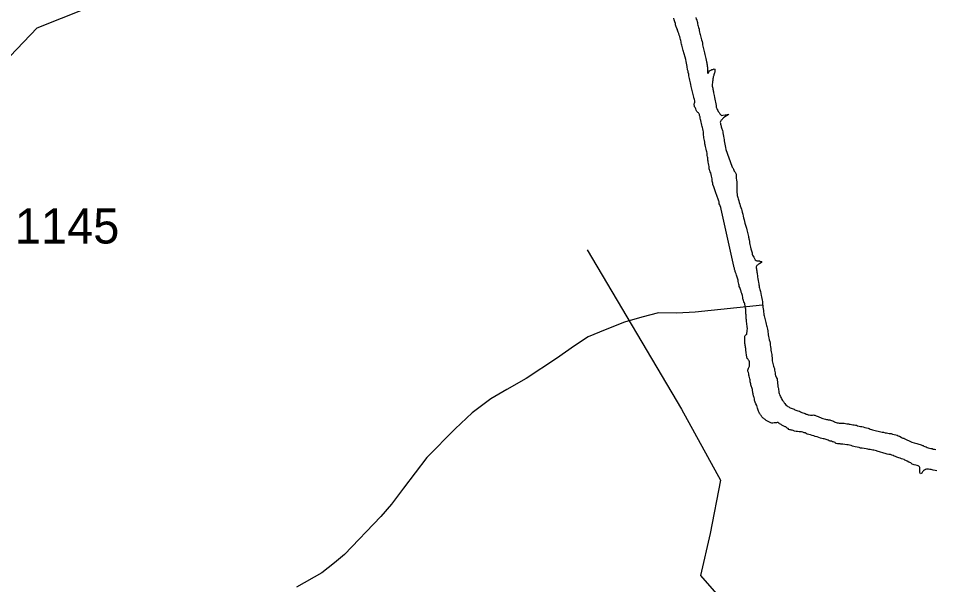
# Model space of a CAD drawing. Extents: x 1662474 to 1856135, y 779280 to 917889.
# Drawn here: x 1727638 to 1730904, y 804884 to 806900 of the extents above; entities that cross this region are included whole.
import ezdxf

# ---------------------------------------------------------------- set-up
doc = ezdxf.new("R2010")
doc.units = 0
for name, color, linetype in [('Exist Hydrographic Lake Shore', 7, 'Continuous'), ('Exist Hydrographic Misc Water Feature', 7, 'Continuous'), ('Exist Road Secondary Type 51 Number Label', 7, 'Continuous'), ('Exist Utilities Electrical Transmission Line', 7, 'Continuous')]:
    doc.layers.add(name, color=color, linetype=linetype)

msp = doc.modelspace()

# ---------------------------------------------------------------- linework, layer by layer
at = {"layer": 'Exist Hydrographic Lake Shore'}
for points in [[(1730046.1, 806584.9), (1730045.4, 806588.1), (1730044.2, 806590.9), (1730044.2, 806593.3), (1730044.9, 806594.9), (1730046.1, 806597.8), (1730046.6, 806600.9), (1730046.4, 806605.6), (1730045.4, 806610.3), (1730044.2, 806614), (1730043.5, 806616.4), (1730042.8, 806619.2), (1730041.9, 806623.8), (1730040.9, 806628.4), (1730040.1, 806633.2), (1730038.8, 806637.9), (1730037.8, 806642.4), (1730035.9, 806647.1), (1730034.9, 806652.3), (1730033.5, 806657.6), (1730032.8, 806663.6), (1730031.8, 806669.7), (1730030.1, 806674.9), (1730029.4, 806679.9), (1730028.2, 806685.1), (1730027.2, 806690.1), (1730025.9, 806695.4), (1730024.9, 806700.6), (1730023.2, 806706.7), (1730022.5, 806711.6), (1730020.9, 806716.4), (1730020.4, 806720.3), (1730019.6, 806724.5), (1730019.4, 806728.7), (1730018.2, 806733.9), (1730017.2, 806740), (1730015.6, 806746.3), (1730014.4, 806752.9), (1730012, 806761.2), (1730008.9, 806773.6), (1730005.1, 806785.7), (1730003.4, 806794.6), (1730002, 806799.8), (1730000.8, 806804.3), (1729999.9, 806808), (1729998.6, 806811.9), (1729997.6, 806816.1), (1729996.8, 806820.3), (1729995.8, 806824.8), (1729994.6, 806829.5), (1729992.9, 806834.8), (1729991.5, 806839.8), (1729989.8, 806845.2), (1729987.6, 806850), (1729986.2, 806853.9), (1729985.2, 806857.6), (1729984.5, 806860.4), (1729983.1, 806863.4), (1729982.1, 806866.8), (1729980.8, 806869.6), (1729979.5, 806873.1), (1729978.4, 806876.8), (1729977.4, 806881.8), (1729975.2, 806887.5), (1729973.1, 806894.1), (1729971.6, 806900.1)], [(1730050.4, 806903), (1730051.9, 806896.9), (1730053.8, 806892.8), (1730054.8, 806888), (1730056.1, 806884.4), (1730056.6, 806879.9), (1730058, 806875.4), (1730059.2, 806871.2), (1730060.2, 806866.5), (1730061.9, 806861.2), (1730062.6, 806856.2), (1730064, 806850.8), (1730064.8, 806846.1), (1730066.1, 806841.8), (1730066.9, 806837.6), (1730067.9, 806833.2), (1730069.8, 806828.4), (1730070.8, 806822.9), (1730072.4, 806816.9), (1730073.6, 806811.4), (1730074.5, 806805.9), (1730075.5, 806801.1), (1730076.9, 806796.4), (1730077.9, 806791.2), (1730079.2, 806786.4), (1730080, 806782), (1730081.2, 806777.2), (1730082.4, 806771.2), (1730083.6, 806765.8), (1730084.8, 806761.8), (1730086.2, 806757.1), (1730087.6, 806751), (1730088.4, 806745.2), (1730089.1, 806740.8), (1730090, 806737.6), (1730090.5, 806733.9), (1730091.2, 806729.5), (1730091.5, 806725.3), (1730092, 806721.1), (1730092, 806718.2), (1730092.4, 806715.1), (1730092, 806711.1), (1730092, 806705.6), (1730093.6, 806702.8), (1730095.8, 806705.9), (1730097.2, 806709), (1730099.1, 806712.4), (1730101.2, 806714.2), (1730104.1, 806715.6), (1730107.5, 806717.2), (1730110.8, 806717.7), (1730112.8, 806719.2), (1730116.2, 806719.5), (1730118, 806719.2)], [(1730118, 806719.2), (1730118.2, 806715.6), (1730118.2, 806713.2), (1730118.2, 806710.9), (1730117.5, 806708.5), (1730116.8, 806705.6), (1730116, 806702.4), (1730114.6, 806699.1), (1730114.1, 806696.2), (1730112.8, 806694.3), (1730112, 806691.4), (1730111.5, 806688), (1730110.8, 806684.4), (1730110.4, 806681.8), (1730110.4, 806678.6), (1730110.1, 806674.9), (1730109.4, 806670.2), (1730108.9, 806665.8), (1730108.9, 806661.2), (1730108.6, 806658.4), (1730109.4, 806655.2), (1730110.4, 806651.6), (1730111.2, 806647.9), (1730112.2, 806644.4), (1730112.5, 806641.3), (1730112.8, 806637.9), (1730113.4, 806634.5), (1730114.4, 806630), (1730115.6, 806624.8), (1730116.8, 806618.2), (1730118, 806611.6), (1730119.4, 806605.9), (1730120.4, 806600.9), (1730121.8, 806595.1), (1730122.5, 806589.1), (1730123.2, 806583.6), (1730125.1, 806578.9), (1730126.1, 806575.2), (1730128.2, 806571.8), (1730130.4, 806568.1), (1730133.2, 806564.4), (1730135.9, 806559.4), (1730138.8, 806556), (1730141.6, 806554.4), (1730146.6, 806554.7), (1730154.8, 806556), (1730162.6, 806557.1), (1730166.4, 806558.1), (1730165.2, 806555.8), (1730162.4, 806553.9), (1730157.1, 806551.3), (1730151.9, 806547.9), (1730148.8, 806546.1), (1730147.4, 806544.4), (1730145.6, 806542.4), (1730144.2, 806540.2), (1730142.8, 806538.7), (1730141.1, 806537.4), (1730139.2, 806534.8), (1730137.8, 806532.1), (1730137.2, 806529.2), (1730137.8, 806526.4), (1730138.2, 806522.7), (1730139.2, 806519.5), (1730140.1, 806516.6), (1730140.9, 806513.2), (1730141.9, 806510.1), (1730143.2, 806506.9), (1730144, 806503.5), (1730145.4, 806499.9), (1730145.9, 806495.6), (1730146.6, 806491.7), (1730148, 806486.8), (1730148.8, 806480.2), (1730149.8, 806473.6), (1730150.9, 806468.9), (1730151.6, 806464.1), (1730152.4, 806458.1), (1730154, 806452.1), (1730154.8, 806446.1), (1730156.1, 806440), (1730157.1, 806432.4), (1730178.4, 806373.6), (1730179.8, 806370.4), (1730182.4, 806367.1), (1730184.8, 806362.8), (1730186.2, 806359.2), (1730187.4, 806355.5), (1730190, 806351.8), (1730192.4, 806347.9), (1730193.9, 806344.8), (1730194.1, 806341.1), (1730194.4, 806336.3), (1730194.4, 806330.8), (1730195.2, 806323.8), (1730195.8, 806317.7), (1730196, 806312.4), (1730196, 806307.8), (1730196, 806302.5), (1730196.2, 806296.4)], [(1730208.1, 805938.7), (1730206.5, 805942.1), (1730204.6, 805945.8), (1730204.1, 805950), (1730202.9, 805953.7), (1730202, 805958.4), (1730201.2, 805963.1), (1730200.5, 805967.3), (1730200.2, 805971.5), (1730199.1, 805975.2), (1730197.6, 805978.6), (1730196, 805982.2), (1730194.6, 805985.9), (1730193.6, 805990.1), (1730192, 805995.1), (1730190.8, 805999.1), (1730190, 806000.9), (1730188.6, 806006.4), (1730187.6, 806011.1), (1730186.2, 806014.8), (1730185.5, 806018.2), (1730141.1, 806220.3), (1730139.2, 806226.9), (1730137.5, 806231.9), (1730135.6, 806236.3), (1730134, 806240), (1730133.5, 806243.2), (1730133.2, 806246.1), (1730132, 806249.2), (1730130.9, 806252.1), (1730130.1, 806256), (1730126.8, 806265.8), (1730120.6, 806282.8), (1730114.4, 806300.1), (1730111.2, 806308.5), (1730110.8, 806312.7), (1730109.6, 806316.1), (1730108.9, 806319.6), (1730108.9, 806324), (1730108.4, 806327.9), (1730107.5, 806332.9), (1730106.5, 806338.4), (1730104.6, 806344.2), (1730103.4, 806349.7), (1730101.2, 806353.9), (1730099.9, 806357.6), (1730098.6, 806360.5), (1730098.1, 806363.6), (1730098.1, 806367.6), (1730097.6, 806372.6), (1730096.2, 806377.6), (1730095.8, 806383.3), (1730094.6, 806387.2), (1730093.9, 806390.9), (1730093.6, 806395.1), (1730093.4, 806398.8), (1730092.6, 806402.8), (1730092.4, 806406.9), (1730091.2, 806411.9), (1730090.8, 806416.6), (1730090.5, 806420.1), (1730089.8, 806424.2), (1730088.1, 806428.4), (1730087.6, 806433.9), (1730086.2, 806439.2), (1730085.2, 806443.9), (1730083.9, 806448.9), (1730082.9, 806453.6), (1730082.1, 806458.9), (1730080.8, 806464.4), (1730080, 806469.1), (1730079.2, 806474.1), (1730078.4, 806479.4), (1730077.6, 806484.1), (1730077.4, 806488.1), (1730077.4, 806491.7), (1730077.4, 806495.6), (1730076.2, 806500.4), (1730075.2, 806505.9), (1730074, 806510.9), (1730072.9, 806515.1), (1730072.1, 806519.2), (1730070.2, 806524.8), (1730068.8, 806530), (1730067.9, 806535.6), (1730066.9, 806539.8), (1730065.8, 806544.4), (1730065.2, 806548.9), (1730064, 806553.4), (1730062.9, 806557.1), (1730061.9, 806559.2), (1730061.4, 806561.2), (1730059.5, 806562.8), (1730058, 806564.1), (1730056.4, 806565.8), (1730054.2, 806568.4), (1730052.1, 806572.8), (1730050.1, 806578.1), (1730047.8, 806581.8), (1730046.1, 806584.9)], [(1730196.2, 806296.4), (1730196.8, 806291.7), (1730196.8, 806286.2), (1730196.8, 806279.9), (1730197, 806273.6), (1730197.2, 806269.1), (1730198.4, 806266), (1730199.6, 806262.3), (1730201.2, 806257.6), (1730203.4, 806250.5), (1730204.6, 806243.9), (1730206.8, 806237.9), (1730208.4, 806232.4), (1730210.4, 806226.1), (1730212.5, 806220.1), (1730214.1, 806215.6), (1730215.6, 806210.4), (1730217.2, 806203.2), (1730218.9, 806195.4), (1730219.9, 806190.1), (1730221.2, 806185.9), (1730222.2, 806182), (1730223.2, 806177.2), (1730224.9, 806170.7), (1730226.8, 806163.6), (1730228, 806159.7), (1730229.4, 806156.8), (1730230.4, 806153.1), (1730232.5, 806146.8), (1730234.2, 806137.1), (1730236.4, 806127.9), (1730238, 806123.2), (1730237.8, 806121.1), (1730238.8, 806116.9), (1730239.5, 806114.8), (1730240.4, 806111.1), (1730240.9, 806105.6), (1730241.1, 806100.4), (1730242.5, 806094.9), (1730243.5, 806090.1), (1730245.4, 806085.7), (1730246.6, 806079.9), (1730248.8, 806072.3), (1730250.4, 806065.2), (1730251.4, 806060.2), (1730252.6, 806056.8), (1730254.2, 806053.7), (1730256.4, 806050), (1730259.5, 806044.8), (1730262.1, 806040), (1730265, 806037.9), (1730267.4, 806036.6), (1730270.8, 806037.1), (1730274.5, 806036.3), (1730277.4, 806036.3), (1730280.5, 806034.5), (1730282.4, 806034), (1730285.8, 806034.2), (1730283.1, 806030.3), (1730280.8, 806028.4), (1730278.4, 806026.6), (1730275.2, 806025.1), (1730272.4, 806023.2), (1730270, 806021.6), (1730267.9, 806019.6), (1730266.9, 806017.7), (1730265.5, 806014.8), (1730265.5, 806011.7), (1730266.1, 806008.2), (1730266.9, 806005.1), (1730267.1, 806000.9), (1730267.6, 805996.2), (1730268.4, 805992.2), (1730269.2, 805989.1), (1730269.8, 805984.9), (1730270.2, 805979.4), (1730271.6, 805972.8), (1730272.6, 805966.2), (1730274, 805959.7), (1730274.5, 805955), (1730274.8, 805951.6), (1730275.5, 805947.1), (1730276, 805943.2), (1730277.4, 805939.8), (1730278.4, 805934.8), (1730280, 805927.7), (1730281.5, 805920.3), (1730282.9, 805913.5), (1730283.9, 805908), (1730285.2, 805902.5), (1730286.2, 805896.7), (1730287.4, 805892), (1730287.6, 805887.2), (1730288.1, 805882.8), (1730288.6, 805878.1), (1730289.1, 805872.3), (1730290, 805866), (1730290.8, 805859.9), (1730291.8, 805854.4), (1730292, 805849.4)], [(1730256.6, 805552.9), (1730256.1, 805556.1), (1730254.5, 805561.8), (1730254, 805563.9), (1730253.8, 805567.3), (1730253.2, 805570.2), (1730252.6, 805572.6), (1730252.4, 805575.7), (1730251.6, 805578.9), (1730250.4, 805582.2), (1730249.2, 805585.7), (1730248.2, 805588.8), (1730247.8, 805592.2), (1730246.6, 805595.7), (1730245.6, 805599.1), (1730244.8, 805602.5), (1730244, 805606.2), (1730244, 805610.4), (1730244, 805613.2), (1730243.2, 805616.9), (1730241.6, 805621.6), (1730240.1, 805626.4), (1730239.5, 805630.3), (1730238.8, 805634.8), (1730238, 805639.5), (1730235.9, 805644.5), (1730235.6, 805647.4), (1730236.4, 805650.8), (1730238, 805654.4), (1730240.1, 805659.2), (1730241.1, 805662.3), (1730241.9, 805666), (1730241.9, 805669.7), (1730241.6, 805673.6), (1730240.9, 805677.6), (1730240.1, 805680.4), (1730238.2, 805683.6), (1730236.6, 805685.7), (1730234.9, 805687.5), (1730233.2, 805689.6), (1730232, 805694.9), (1730230.6, 805700.4), (1730230.4, 805703.6), (1730229.6, 805707.5), (1730229.4, 805712.2), (1730228.2, 805717.7), (1730228, 805721.9), (1730227.8, 805724.8), (1730227.2, 805728.5), (1730226.8, 805731.9), (1730226.5, 805735.6), (1730225.6, 805739.2), (1730225.1, 805742.1), (1730224.4, 805746.3), (1730224.4, 805751.3), (1730224.4, 805755.8), (1730224.9, 805759.4), (1730224.9, 805762.3), (1730224.4, 805766), (1730224.4, 805768.4), (1730226.5, 805770.4), (1730228.8, 805772.8), (1730230.6, 805774.7), (1730232, 805776), (1730232.2, 805779.6), (1730232.5, 805782.2), (1730232.8, 805784.1), (1730233.5, 805787), (1730233.5, 805789.4), (1730233.8, 805794.9), (1730233.2, 805803), (1730232, 805812.8), (1730230.6, 805821.9), (1730230.4, 805826.9), (1730230.1, 805830.3), (1730229.6, 805836.1), (1730229.6, 805841.6), (1730229.4, 805844.8), (1730228.8, 805848.4), (1730228.2, 805855.5), (1730228, 805861.6), (1730227.8, 805865.2), (1730227.2, 805868.6), (1730226.5, 805873.4), (1730225.6, 805878.1), (1730224.9, 805880.4), (1730224.4, 805883.1), (1730223.2, 805887), (1730221.8, 805891.2), (1730219.9, 805895.4), (1730219.4, 805898.8), (1730218.2, 805901.9), (1730217.2, 805906.4), (1730216, 805913.5), (1730213.6, 805920.1), (1730212.2, 805925.3), (1730211.8, 805928.8), (1730210.8, 805931.6), (1730209.4, 805934.5), (1730208.1, 805938.7)], [(1730292, 805849.4), (1730292.9, 805844.5), (1730293.6, 805841.1), (1730294.4, 805836.3), (1730295.8, 805831.1), (1730297.2, 805826.4), (1730298.4, 805821.9), (1730299.6, 805817.7), (1730300.8, 805811.7), (1730302, 805806.7), (1730302.9, 805802.8), (1730304.4, 805798.3), (1730305.5, 805793.6), (1730306.5, 805788.1), (1730306.8, 805783.1), (1730307.5, 805777.6), (1730308.4, 805772.8), (1730309.6, 805767.6), (1730310.8, 805762.1), (1730312, 805756), (1730313.6, 805749.8), (1730314.6, 805743.7), (1730315.6, 805737.6), (1730316.5, 805731.1), (1730317.2, 805724.6), (1730317.8, 805718.8), (1730318.9, 805713.2), (1730319.6, 805707.8), (1730320.4, 805702.8), (1730320.6, 805697.2), (1730321.8, 805691.8), (1730322, 805685.9), (1730322.5, 805680.9), (1730323.5, 805676.2), (1730324.1, 805671.5), (1730325.1, 805666.2), (1730326.4, 805662.3), (1730328, 805658.4), (1730329.9, 805653.1), (1730330.6, 805648.1), (1730332, 805642.9), (1730332.5, 805637.9), (1730332.8, 805632.4), (1730334, 805627.9), (1730335.9, 805624), (1730338, 805620.3), (1730339.5, 805616.4), (1730340.4, 805611.7), (1730341.1, 805605.6), (1730341.6, 805600.1), (1730341.9, 805594.4), (1730342.5, 805588.8), (1730343.2, 805585.4), (1730344.2, 805581.2), (1730344.8, 805577.3), (1730345.4, 805572.8), (1730346.4, 805568.6), (1730347.4, 805564.4), (1730348.2, 805562.1), (1730349.5, 805557.6), (1730351.4, 805553.9), (1730353, 805550.5), (1730354.8, 805547.1), (1730356.6, 805543.4), (1730359.2, 805539.2), (1730361.9, 805535.6), (1730364.5, 805531.9), (1730366.9, 805528.8), (1730369.8, 805525.9), (1730372.4, 805522.4), (1730375.2, 805520.3), (1730378.4, 805518), (1730381.2, 805516.9), (1730383.9, 805515.1), (1730386.8, 805514.1), (1730389.8, 805512.8), (1730393.4, 805511.4), (1730396.8, 805510.1), (1730399.9, 805508.2), (1730402.5, 805506.9), (1730405.8, 805505.6), (1730409.6, 805504.3), (1730414.1, 805502.8), (1730418.9, 805501.2), (1730423.2, 805499.1), (1730427.2, 805497.2), (1730431.6, 805495.4), (1730435.6, 805494.1), (1730439.2, 805492.8), (1730442.8, 805491.4), (1730446.1, 805490.4), (1730450, 805488.8), (1730454, 805488.3), (1730458.5, 805487.5), (1730462.4, 805487.2), (1730465.5, 805487.2), (1730468.8, 805488.1), (1730471.6, 805487.8), (1730474, 805487.2), (1730476.2, 805485.7)], [(1730563.8, 805384.9), (1730559.5, 805385.2), (1730554.8, 805385.4), (1730550.4, 805386.2), (1730547.8, 805388.1), (1730545.9, 805389.9), (1730542.5, 805391.2), (1730539.5, 805392.5), (1730537.2, 805393.1), (1730534.9, 805394.4), (1730532, 805394.4), (1730528.2, 805395.1), (1730524.9, 805396.4), (1730521.1, 805398), (1730517.5, 805399.1), (1730514.4, 805400.4), (1730510.6, 805401.7), (1730507.2, 805402.8), (1730503.4, 805403.6), (1730499.1, 805404.3), (1730493.9, 805405.9), (1730488.1, 805408.2), (1730481.9, 805410.1), (1730475.5, 805411.1), (1730470, 805413.5), (1730464.5, 805414.8), (1730458.5, 805416.9), (1730452.4, 805418.8), (1730447.1, 805420.1), (1730443.2, 805422.4), (1730439.2, 805424), (1730435.6, 805424.6), (1730431.1, 805426.6), (1730426.8, 805427.7), (1730422.5, 805428.5), (1730418, 805428.5), (1730412.8, 805429), (1730407.5, 805429.2), (1730402, 805430.8), (1730397.2, 805432.4), (1730393.4, 805433.8), (1730390, 805434.2), (1730387.4, 805435.1), (1730384.5, 805435.6), (1730381.5, 805436.9), (1730378.6, 805439.5), (1730375.2, 805441.6), (1730372.6, 805443.7), (1730370.2, 805445.6), (1730367.9, 805446.3), (1730364, 805447.9), (1730360.9, 805449.8), (1730357.1, 805451.3), (1730353.8, 805453.9), (1730351.4, 805455.8), (1730348.8, 805456.8), (1730345.6, 805459.4), (1730342.8, 805460.8), (1730339.5, 805460.8), (1730337.2, 805460.2), (1730335.4, 805459.7), (1730331.6, 805459.7), (1730328.8, 805460), (1730324.9, 805459.2), (1730321.1, 805459.2), (1730317.8, 805460), (1730315.1, 805461.6), (1730312.8, 805462.1), (1730310.4, 805463.4), (1730308.1, 805464.4), (1730305.8, 805466), (1730302.9, 805467.1), (1730300.5, 805468.9), (1730297.6, 805471.5), (1730294.6, 805473.4), (1730292.4, 805475.2), (1730290.5, 805476.5), (1730288.1, 805478.9), (1730285.8, 805481.5), (1730283.6, 805483.3), (1730282.4, 805486.2), (1730281, 805488.1), (1730279.2, 805490.9), (1730277.6, 805493.6), (1730276.2, 805496.4), (1730275.2, 805498.8), (1730274, 805501.9), (1730272.6, 805504.9), (1730271.6, 805508.8), (1730270.2, 805512.8), (1730268.8, 805517.2), (1730267.4, 805521.9), (1730264.2, 805527.7), (1730261.9, 805533.8), (1730260.2, 805537.4), (1730259.5, 805539.2), (1730259, 805542.4), (1730258.8, 805546.1), (1730257.6, 805550), (1730256.6, 805552.9)], [(1730476.2, 805485.7), (1730479.2, 805485.2), (1730482.9, 805484.4), (1730486.2, 805482.6), (1730490.2, 805480.7), (1730494.6, 805478.6), (1730498.9, 805477.3), (1730502.8, 805476), (1730506.8, 805474.9), (1730512, 805473.4), (1730515.9, 805472.3), (1730519.4, 805471.5), (1730522, 805470.8), (1730524.9, 805470.5), (1730527.8, 805470.8), (1730530.1, 805469.9), (1730532.8, 805468.9), (1730536.6, 805467.1), (1730540.9, 805466), (1730544, 805463.6), (1730546.4, 805462.3), (1730550, 805461), (1730553.8, 805460), (1730556.6, 805459.7), (1730560.9, 805459.2), (1730565.2, 805459.2), (1730570.2, 805459.2), (1730574.8, 805459.2), (1730578.6, 805458.4), (1730583.6, 805457.6), (1730587.6, 805457.1), (1730590.8, 805456.8), (1730593.4, 805456.1), (1730596, 805455.5), (1730599.9, 805454.8), (1730604.6, 805453.9), (1730609.9, 805453.1), (1730614.6, 805452.9), (1730618.9, 805452.1), (1730622.8, 805451.3), (1730626.4, 805449.8), (1730631.6, 805448.7), (1730636.4, 805447.6), (1730640.9, 805446.9), (1730646.1, 805446.1), (1730651.9, 805443.7), (1730657.6, 805442.4), (1730663.8, 805440.8), (1730667.9, 805439.8), (1730671.6, 805437.7), (1730675.5, 805436.4), (1730679.8, 805434.8), (1730684.1, 805433.8), (1730688.9, 805432.9), (1730693.9, 805431.6), (1730699.1, 805430.3), (1730704.4, 805429), (1730709.4, 805427.9), (1730713.6, 805427.2), (1730719.1, 805426.4), (1730724.4, 805424.8), (1730729.4, 805424.2), (1730734, 805423.8), (1730738.5, 805422.7), (1730742.5, 805422.7), (1730746.1, 805421.9), (1730750.4, 805420.3), (1730756.4, 805418.8), (1730762.1, 805417.2), (1730766.6, 805415.9), (1730770.2, 805414.3), (1730775.8, 805412.2), (1730781.2, 805409.6), (1730785.2, 805407.2), (1730787.9, 805405.9), (1730790.8, 805405.1), (1730792.6, 805403.8), (1730819.9, 805391.8), (1730828, 805389.1), (1730832.8, 805387.8), (1730837.2, 805386.5), (1730840.9, 805385.2), (1730844.2, 805384.1), (1730848.8, 805382.6), (1730853.2, 805381.5), (1730856.9, 805379.9), (1730859.2, 805378.9), (1730862.4, 805377.3), (1730866, 805376), (1730870, 805374.4), (1730873.6, 805372.8), (1730877.9, 805371), (1730882.1, 805369.9), (1730886.8, 805369.2), (1730891.5, 805368.4), (1730895.8, 805366.8), (1730899.6, 805366.2), (1730904.4, 805364.7)], [(1730908.9, 805288.9), (1730902.2, 805290.2), (1730895.2, 805291.5), (1730888.4, 805293.6), (1730882.9, 805294.4), (1730878.4, 805295.7), (1730875.2, 805295.7), (1730872.1, 805295.1), (1730868.6, 805294.1), (1730864.8, 805292.2), (1730861.1, 805290.2), (1730859.2, 805287.8), (1730857.6, 805286.2), (1730856.4, 805283.6), (1730855, 805281.5), (1730852.4, 805279.7), (1730850.6, 805279.1), (1730848.8, 805281), (1730848, 805283.6), (1730848, 805288.1), (1730848, 805292.2), (1730847.6, 805295.4), (1730847.6, 805298.3), (1730847.6, 805300.6), (1730846.6, 805303.2), (1730844.8, 805305.9), (1730841.6, 805307.5), (1730838.5, 805308), (1730833.2, 805309.3), (1730828, 805310.4), (1730824.4, 805311.4), (1730820.4, 805313.2), (1730815.4, 805317.2), (1730808.9, 805320.3), (1730802.8, 805323.5), (1730798.1, 805325.6), (1730794.6, 805327.7), (1730791.5, 805329.2), (1730787.4, 805330.8), (1730782.4, 805332.4), (1730777.6, 805334.2), (1730773.1, 805335.6), (1730770, 805336.4), (1730766.4, 805337.9), (1730761.6, 805340), (1730756.4, 805341.9), (1730752.4, 805343.9), (1730748, 805345.2), (1730743.2, 805346.9), (1730737.2, 805347.9), (1730732, 805349.2), (1730727.8, 805350), (1730696.5, 805358.9), (1730693.4, 805360), (1730688.4, 805361.3), (1730684.1, 805362.3), (1730680.5, 805363.1), (1730676.2, 805363.9), (1730671.2, 805364.7), (1730666.4, 805365.8), (1730662.4, 805366.2), (1730657.1, 805367.1), (1730650, 805368.4), (1730642.8, 805369.7), (1730636.6, 805370.5), (1730631.6, 805371.8), (1730624.9, 805373.9), (1730618, 805375.2), (1730612.8, 805376), (1730608, 805377.6), (1730602.8, 805379.1), (1730597.5, 805380.7), (1730592.2, 805382), (1730587.4, 805382), (1730580.5, 805382.8), (1730573.6, 805384.1), (1730569.8, 805384.4), (1730567.1, 805384.4), (1730563.8, 805384.9)]]:
    msp.add_lwpolyline(points, dxfattribs=at)
at = {"layer": 'Exist Hydrographic Misc Water Feature'}
for points in [[(1726547.4, 806902.8), (1727052.4, 806531.5), (1727127.5, 806507), (1727319.4, 806535.9), (1727461.5, 806611.8), (1727705.5, 806866.1), (1728057.6, 807006.7)], [(1730288.2, 805878.6), (1730048.2, 805854.3), (1729982.2, 805850.9), (1729918, 805851.5), (1729857.9, 805836), (1729795.8, 805818.7), (1729727.5, 805791.3), (1729667.2, 805765.8), (1729618.8, 805734.3), (1729554.4, 805688.9), (1729445.8, 805617.9), (1729377.3, 805578.5), (1729320.9, 805545), (1729254.5, 805495.6), (1729194, 805438.2), (1729093.1, 805337.1), (1729009.8, 805227.9), (1728967.4, 805170.3), (1728928.8, 805126.6), (1728799.7, 804991.8), (1728763.4, 804962.1), (1728719.1, 804926.6), (1728628.4, 804875.4)]]:
    msp.add_lwpolyline(points, dxfattribs=at)
at = {"layer": 'Exist Utilities Electrical Transmission Line'}
msp.add_lwpolyline([(1729663.4, 806075.3), (1729999.5, 805509.1), (1730137.7, 805255.6), (1730101.1, 805066.3), (1730067.2, 804916.6), (1730197, 804766.9), (1730349.1, 804495.3), (1730544.5, 804162.8), (1730583.4, 804090.5), (1730529.6, 803381.9), (1730486.5, 803004.7)], dxfattribs=at)

# ---------------------------------------------------------------- texts
at = {"layer": 'Exist Road Secondary Type 51 Number Label'}
msp.add_text('1145', height=125, dxfattribs=at).set_placement((1727625.9, 806098.3))

doc.saveas('drawing.dxf')
